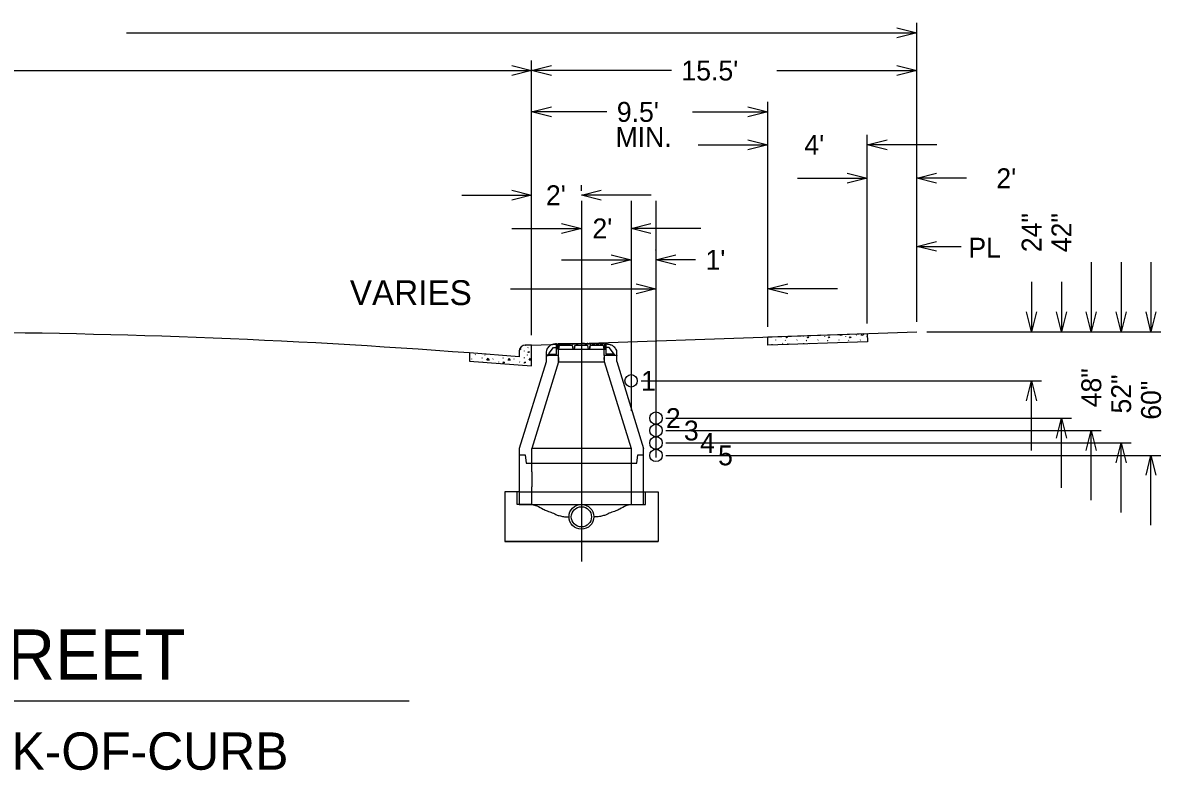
# Model space of a CAD drawing. Extents: x 524397 to 525117, y 3701341 to 3701821.
# Drawn here: x 524541.9 to 524633.5, y 3701606.9 to 3701667.1 of the extents above; entities that cross this region are included whole.
import ezdxf

# ---------------------------------------------------------------- set-up
doc = ezdxf.new("R2010")
doc.units = 0
doc.layers.add('Level 1', color=7, linetype='Continuous')
doc.layers.add('Level 11', color=7, linetype='Continuous')

msp = doc.modelspace()

# ---------------------------------------------------------------- linework, layer by layer
at = {"layer": 'Level 1'}
msp.add_line((524483.617, 3701612.509), (524573.018, 3701612.509), dxfattribs=at)
at = {"layer": 'Level 11'}
for p, q in [((524550.265, 3701666.282), (524613.852, 3701666.282)), ((524612.251, 3701666.682), (524613.852, 3701666.282)), ((524613.852, 3701666.282), (524612.251, 3701665.882)), ((524613.852, 3701643.021), (524613.852, 3701667.083)), ((524581.27, 3701663.64), (524582.871, 3701663.24)), ((524582.871, 3701641.938), (524582.871, 3701664.041)), ((524582.871, 3701663.24), (524584.472, 3701663.64)), ((524612.251, 3701663.64), (524613.852, 3701663.24)), ((524613.852, 3701643.021), (524613.852, 3701664.041)), ((524536.524, 3701663.24), (524582.871, 3701663.24)), ((524582.871, 3701663.24), (524581.27, 3701662.84)), ((524594.12, 3701663.24), (524582.871, 3701663.24)), ((524584.472, 3701662.84), (524582.871, 3701663.24)), ((524602.603, 3701663.24), (524613.852, 3701663.24)), ((524613.852, 3701663.24), (524612.251, 3701662.84)), ((524582.871, 3701641.937), (524582.871, 3701660.711)), ((524601.871, 3701642.602), (524601.871, 3701660.711)), ((524582.871, 3701659.911), (524584.472, 3701660.311)), ((524588.923, 3701659.911), (524582.871, 3701659.911)), ((524584.472, 3701659.511), (524582.871, 3701659.911)), ((524595.819, 3701659.911), (524601.871, 3701659.911)), ((524600.27, 3701660.311), (524601.871, 3701659.911)), ((524601.871, 3701659.911), (524600.27, 3701659.511)), ((524601.871, 3701652.457), (524601.871, 3701658.057)), ((524609.866, 3701642.881), (524609.866, 3701658.057)), ((524596.267, 3701657.256), (524601.871, 3701657.256)), ((524600.27, 3701657.656), (524601.871, 3701657.256)), ((524601.871, 3701657.256), (524600.27, 3701656.856)), ((524609.866, 3701657.256), (524611.467, 3701657.656)), ((524615.47, 3701657.256), (524609.866, 3701657.256)), ((524611.467, 3701656.856), (524609.866, 3701657.256)), ((524609.866, 3701651.269), (524609.866, 3701655.37)), ((524613.853, 3701643.021), (524613.853, 3701655.37)), ((524604.263, 3701654.569), (524609.866, 3701654.569)), ((524608.265, 3701654.97), (524609.866, 3701654.569)), ((524609.866, 3701654.569), (524608.265, 3701654.169)), ((524613.853, 3701654.569), (524615.454, 3701654.97)), ((524617.855, 3701654.569), (524613.853, 3701654.569)), ((524615.454, 3701654.169), (524613.853, 3701654.569)), ((524581.27, 3701653.603), (524582.871, 3701653.202)), ((524582.871, 3701641.937), (524582.871, 3701654.003)), ((524586.871, 3701653.553), (524586.871, 3701654.003)), ((524586.871, 3701653.202), (524588.472, 3701653.603)), ((524577.267, 3701653.202), (524582.871, 3701653.202)), ((524582.871, 3701653.202), (524581.27, 3701652.802)), ((524592.475, 3701653.202), (524586.871, 3701653.202)), ((524588.472, 3701652.802), (524586.871, 3701653.202)), ((524586.871, 3701652.752), (524586.871, 3701623.725)), ((524590.871, 3701652.752), (524590.871, 3701635.855)), ((524592.871, 3701652.752), (524592.871, 3701632.088)), ((524585.27, 3701650.933), (524586.871, 3701650.533)), ((524590.871, 3701650.533), (524592.472, 3701650.933)), ((524581.267, 3701650.533), (524586.871, 3701650.533)), ((524586.871, 3701650.533), (524585.27, 3701650.133)), ((524586.871, 3701649.77), (524586.871, 3701649.733)), ((524596.475, 3701650.533), (524590.871, 3701650.533)), ((524592.472, 3701650.133), (524590.871, 3701650.533)), ((524590.871, 3701649.812), (524590.871, 3701649.733)), ((524592.871, 3701648.778), (524592.871, 3701648.806)), ((524613.852, 3701649.092), (524615.453, 3701649.492)), ((524613.852, 3701649.092), (524617.42, 3701649.092)), ((524615.453, 3701648.692), (524613.852, 3701649.092)), ((524585.267, 3701648.005), (524590.871, 3701648.005)), ((524589.27, 3701648.406), (524590.871, 3701648.005)), ((524590.871, 3701648.005), (524589.27, 3701647.605)), ((524592.871, 3701648.005), (524594.472, 3701648.406)), ((524596.056, 3701648.005), (524592.871, 3701648.005)), ((524594.472, 3701647.605), (524592.871, 3701648.005)), ((524590.871, 3701647.261), (524590.871, 3701647.205)), ((524627.895, 3701647.824), (524627.895, 3701642.22)), ((524630.297, 3701647.824), (524630.297, 3701642.22)), ((524632.698, 3701647.824), (524632.698, 3701642.22)), ((524591.27, 3701646.08), (524592.871, 3701645.68)), ((524601.871, 3701643.402), (524601.871, 3701646.48)), ((524601.871, 3701645.68), (524603.472, 3701646.08)), ((524623.093, 3701646.223), (524623.093, 3701642.22)), ((524625.494, 3701646.223), (524625.494, 3701642.22)), ((524581.162, 3701645.68), (524592.871, 3701645.68)), ((524592.871, 3701645.68), (524591.27, 3701645.28)), ((524607.475, 3701645.68), (524601.871, 3701645.68)), ((524603.472, 3701645.28), (524601.871, 3701645.68)), ((524592.871, 3701644.92), (524592.871, 3701644.88)), ((524623.093, 3701642.22), (524622.692, 3701643.821)), ((524623.493, 3701643.821), (524623.093, 3701642.22)), ((524625.494, 3701642.22), (524625.094, 3701643.821)), ((524625.894, 3701643.821), (524625.494, 3701642.22)), ((524627.895, 3701642.22), (524627.495, 3701643.821)), ((524628.296, 3701643.821), (524627.895, 3701642.22)), ((524630.297, 3701642.22), (524629.897, 3701643.821)), ((524630.697, 3701643.821), (524630.297, 3701642.22)), ((524632.698, 3701642.22), (524632.298, 3701643.821)), ((524633.098, 3701643.821), (524632.698, 3701642.22)), ((524582.871, 3701641.137), (524613.852, 3701642.221)), ((524601.871, 3701641.802), (524609.866, 3701642.081)), ((524601.871, 3701641.141), (524601.871, 3701641.802)), ((524602.504, 3701641.536), (524602.518, 3701641.568)), ((524603.027, 3701641.842), (524603.028, 3701641.826)), ((524603.267, 3701641.536), (524603.281, 3701641.514)), ((524603.281, 3701641.528), (524603.296, 3701641.506)), ((524604.205, 3701641.536), (524604.219, 3701641.568)), ((524604.726, 3701641.858), (524604.73, 3701641.826)), ((524604.969, 3701641.536), (524604.983, 3701641.514)), ((524604.983, 3701641.528), (524604.997, 3701641.506)), ((524605.907, 3701641.536), (524605.921, 3701641.568)), ((524606.428, 3701641.858), (524606.431, 3701641.826)), ((524606.67, 3701641.536), (524606.684, 3701641.514)), ((524606.684, 3701641.528), (524606.699, 3701641.506)), ((524607.285, 3701641.948), (524607.299, 3701641.98)), ((524607.608, 3701641.536), (524607.622, 3701641.568)), ((524608.129, 3701641.858), (524608.133, 3701641.826)), ((524608.372, 3701641.536), (524608.386, 3701641.514)), ((524608.386, 3701641.528), (524608.4, 3701641.506)), ((524608.986, 3701641.948), (524609.001, 3701641.98)), ((524609.31, 3701641.536), (524609.324, 3701641.568)), ((524609.831, 3701641.858), (524609.834, 3701641.826)), ((524609.866, 3701642.081), (524609.889, 3701641.421)), ((524614.653, 3701642.22), (524623.893, 3701642.22)), ((524614.653, 3701642.22), (524626.294, 3701642.22)), ((524614.653, 3701642.22), (524628.696, 3701642.22)), ((524614.653, 3701642.22), (524631.097, 3701642.22)), ((524614.653, 3701642.22), (524633.499, 3701642.22)), ((524581.871, 3701640.675), (524581.871, 3701640.213)), ((524582.26, 3701640.689), (524582.263, 3701640.657)), ((524582.871, 3701641.138), (524582.358, 3701641.138)), ((524582.358, 3701641.138), (524582.371, 3701641.138)), ((524582.577, 3701640.924), (524582.591, 3701640.956)), ((524582.871, 3701639.476), (524582.871, 3701641.138)), ((524584.289, 3701640.507), (524584.639, 3701640.945)), ((524584.639, 3701640.945), (524584.872, 3701640.944)), ((524584.872, 3701641.235), (524584.872, 3701641.235)), ((524584.872, 3701641.235), (524584.955, 3701641.235)), ((524584.872, 3701640.944), (524584.872, 3701641.235)), ((524584.872, 3701640.403), (524584.872, 3701640.944)), ((524584.955, 3701640.819), (524584.955, 3701641.235)), ((524585.038, 3701640.819), (524584.955, 3701640.819)), ((524584.997, 3701641.235), (524584.997, 3701640.819)), ((524585.039, 3701641.235), (524584.997, 3701641.235)), ((524584.997, 3701641.235), (524585.039, 3701641.235)), ((524584.997, 3701640.819), (524584.997, 3701641.235)), ((524584.997, 3701640.819), (524588.744, 3701640.819)), ((524585.038, 3701640.819), (524584.997, 3701640.819)), ((524585.038, 3701640.819), (524585.09, 3701641.111)), ((524585.09, 3701641.111), (524585.038, 3701640.819)), ((524585.038, 3701640.319), (524585.038, 3701640.819)), ((524585.039, 3701641.235), (524585.054, 3701641.277)), ((524585.039, 3701641.235), (524585.054, 3701641.277)), ((524585.054, 3701641.277), (524585.117, 3701641.277)), ((524585.054, 3701641.277), (524585.117, 3701641.277)), ((524586.153, 3701641.111), (524585.09, 3701641.111)), ((524586.153, 3701641.111), (524585.09, 3701641.111)), ((524585.132, 3701641.235), (524585.117, 3701641.277)), ((524585.117, 3701641.277), (524585.132, 3701641.235)), ((524585.363, 3701641.235), (524585.132, 3701641.235)), ((524585.132, 3701641.235), (524585.363, 3701641.235)), ((524585.363, 3701641.235), (524585.378, 3701641.277)), ((524585.363, 3701641.235), (524585.378, 3701641.277)), ((524585.378, 3701641.277), (524585.438, 3701641.277)), ((524585.378, 3701641.277), (524585.438, 3701641.277)), ((524585.453, 3701641.235), (524585.438, 3701641.277)), ((524585.438, 3701641.277), (524585.453, 3701641.235)), ((524585.679, 3701641.235), (524585.453, 3701641.235)), ((524585.453, 3701641.235), (524585.679, 3701641.235)), ((524585.679, 3701641.235), (524585.694, 3701641.277)), ((524585.679, 3701641.235), (524585.694, 3701641.277)), ((524585.694, 3701641.277), (524585.762, 3701641.277)), ((524585.694, 3701641.277), (524585.762, 3701641.277)), ((524585.777, 3701641.235), (524585.762, 3701641.277)), ((524585.762, 3701641.277), (524585.777, 3701641.235)), ((524586.006, 3701641.235), (524585.777, 3701641.235)), ((524585.777, 3701641.235), (524586.006, 3701641.235)), ((524586.006, 3701641.235), (524586.022, 3701641.277)), ((524586.006, 3701641.235), (524586.022, 3701641.277)), ((524586.022, 3701641.277), (524586.087, 3701641.277)), ((524586.022, 3701641.277), (524586.087, 3701641.277)), ((524586.102, 3701641.235), (524586.087, 3701641.277)), ((524586.087, 3701641.277), (524586.102, 3701641.235)), ((524586.329, 3701641.235), (524586.102, 3701641.235)), ((524586.102, 3701641.235), (524586.329, 3701641.235)), ((524586.204, 3701640.819), (524586.153, 3701641.111)), ((524586.204, 3701640.819), (524586.153, 3701641.111)), ((524586.288, 3701640.819), (524586.204, 3701640.819)), ((524586.288, 3701640.819), (524586.339, 3701641.111)), ((524586.339, 3701641.111), (524586.288, 3701640.819)), ((524586.329, 3701641.235), (524586.344, 3701641.277)), ((524586.329, 3701641.235), (524586.344, 3701641.277)), ((524587.402, 3701641.111), (524586.339, 3701641.111)), ((524587.402, 3701641.111), (524586.339, 3701641.111)), ((524586.344, 3701641.277), (524586.402, 3701641.277)), ((524586.344, 3701641.277), (524586.402, 3701641.277)), ((524586.418, 3701641.235), (524586.402, 3701641.277)), ((524586.402, 3701641.277), (524586.418, 3701641.235)), ((524586.604, 3701641.235), (524586.418, 3701641.235)), ((524586.418, 3701641.235), (524586.604, 3701641.235)), ((524586.604, 3701641.235), (524586.62, 3701641.277)), ((524586.604, 3701641.235), (524586.62, 3701641.277)), ((524586.62, 3701641.277), (524586.87, 3701641.277)), ((524586.62, 3701641.277), (524587.122, 3701641.277)), ((524587.122, 3701641.277), (524586.87, 3701641.277)), ((524587.137, 3701641.235), (524587.122, 3701641.277)), ((524587.122, 3701641.277), (524587.137, 3701641.235)), ((524587.324, 3701641.235), (524587.137, 3701641.235)), ((524587.137, 3701641.235), (524587.324, 3701641.235)), ((524587.324, 3701641.235), (524587.339, 3701641.277)), ((524587.324, 3701641.235), (524587.339, 3701641.277)), ((524587.397, 3701641.277), (524587.339, 3701641.277)), ((524587.339, 3701641.277), (524587.397, 3701641.277)), ((524587.412, 3701641.235), (524587.397, 3701641.277)), ((524587.397, 3701641.277), (524587.412, 3701641.235)), ((524587.454, 3701640.819), (524587.402, 3701641.111)), ((524587.454, 3701640.819), (524587.402, 3701641.111)), ((524587.639, 3701641.235), (524587.412, 3701641.235)), ((524587.412, 3701641.235), (524587.639, 3701641.235)), ((524587.537, 3701640.819), (524587.454, 3701640.819)), ((524587.537, 3701640.819), (524587.588, 3701641.111)), ((524587.588, 3701641.111), (524587.537, 3701640.819)), ((524588.651, 3701641.111), (524587.588, 3701641.111)), ((524588.432, 3701641.111), (524587.588, 3701641.111)), ((524587.639, 3701641.235), (524587.655, 3701641.277)), ((524587.639, 3701641.235), (524587.655, 3701641.277)), ((524587.72, 3701641.277), (524587.655, 3701641.277)), ((524587.655, 3701641.277), (524587.72, 3701641.277)), ((524587.735, 3701641.235), (524587.72, 3701641.277)), ((524587.72, 3701641.277), (524587.735, 3701641.235)), ((524587.964, 3701641.235), (524587.735, 3701641.235)), ((524587.735, 3701641.235), (524587.964, 3701641.235)), ((524587.964, 3701641.235), (524587.979, 3701641.277)), ((524587.964, 3701641.235), (524587.979, 3701641.277)), ((524588.047, 3701641.277), (524587.979, 3701641.277)), ((524587.979, 3701641.277), (524588.047, 3701641.277)), ((524588.062, 3701641.235), (524588.047, 3701641.277)), ((524588.047, 3701641.277), (524588.062, 3701641.235)), ((524588.289, 3701641.235), (524588.062, 3701641.235)), ((524588.062, 3701641.235), (524588.289, 3701641.235)), ((524588.289, 3701641.235), (524588.303, 3701641.277)), ((524588.289, 3701641.235), (524588.303, 3701641.277)), ((524588.363, 3701641.277), (524588.303, 3701641.277)), ((524588.303, 3701641.277), (524588.363, 3701641.277)), ((524588.378, 3701641.235), (524588.363, 3701641.277)), ((524588.363, 3701641.277), (524588.378, 3701641.235)), ((524588.609, 3701641.235), (524588.378, 3701641.235)), ((524588.378, 3701641.235), (524588.432, 3701641.235)), ((524588.432, 3701641.235), (524588.432, 3701641.111)), ((524588.432, 3701641.235), (524588.432, 3701641.111)), ((524588.557, 3701641.235), (524588.557, 3701641.111)), ((524588.557, 3701641.235), (524588.609, 3701641.235)), ((524588.557, 3701641.111), (524588.557, 3701641.235)), ((524588.651, 3701641.111), (524588.557, 3701641.111)), ((524588.609, 3701641.235), (524588.625, 3701641.277)), ((524588.609, 3701641.235), (524588.625, 3701641.277)), ((524588.687, 3701641.277), (524588.625, 3701641.277)), ((524588.625, 3701641.277), (524588.687, 3701641.277)), ((524588.703, 3701640.819), (524588.651, 3701641.111)), ((524588.703, 3701640.819), (524588.651, 3701641.111)), ((524588.702, 3701641.235), (524588.687, 3701641.277)), ((524588.687, 3701641.277), (524588.702, 3701641.235)), ((524588.744, 3701641.235), (524588.702, 3701641.235)), ((524588.702, 3701641.235), (524588.744, 3701641.235)), ((524588.703, 3701640.319), (524588.703, 3701640.819)), ((524588.703, 3701640.819), (524588.786, 3701640.819)), ((524588.744, 3701640.819), (524588.703, 3701640.819)), ((524588.744, 3701641.235), (524588.744, 3701640.819)), ((524588.744, 3701641.235), (524588.744, 3701640.819)), ((524588.786, 3701640.819), (524588.786, 3701641.235)), ((524588.869, 3701641.235), (524588.786, 3701641.235)), ((524588.869, 3701640.944), (524588.869, 3701641.235)), ((524589.102, 3701640.945), (524588.869, 3701640.944)), ((524588.869, 3701640.403), (524588.869, 3701640.944)), ((524589.452, 3701640.507), (524589.102, 3701640.945)), ((524609.889, 3701641.421), (524601.871, 3701641.141)), ((524602.216, 3701641.191), (524602.23, 3701641.223)), ((524603.058, 3701641.272), (524603.072, 3701641.304)), ((524603.927, 3701641.213), (524603.932, 3701641.223)), ((524604.759, 3701641.272), (524604.773, 3701641.304)), ((524606.474, 3701641.302), (524606.475, 3701641.304)), ((524581.871, 3701640.213), (524577.871, 3701640.515)), ((524577.871, 3701640.515), (524577.871, 3701639.853)), ((524577.871, 3701639.853), (524582.871, 3701639.476)), ((524578.048, 3701640.021), (524578.062, 3701640.053)), ((524578.336, 3701640.366), (524578.35, 3701640.398)), ((524578.89, 3701640.103), (524578.904, 3701640.135)), ((524579.099, 3701640.366), (524579.113, 3701640.345)), ((524579.113, 3701640.358), (524579.128, 3701640.337)), ((524579.749, 3701640.021), (524579.764, 3701640.053)), ((524580.193, 3701639.794), (524580.208, 3701639.773)), ((524580.591, 3701640.103), (524580.605, 3701640.135)), ((524581.451, 3701640.021), (524581.465, 3701640.053)), ((524584.028, 3701639.786), (524581.878, 3701632.819)), ((524581.895, 3701639.794), (524581.909, 3701639.773)), ((524582.293, 3701640.103), (524582.307, 3701640.135)), ((524582.502, 3701640.366), (524582.516, 3701640.345)), ((524582.516, 3701640.358), (524582.531, 3701640.337)), ((524585.028, 3701639.787), (524582.877, 3701632.819)), ((524584.028, 3701640.319), (524584.028, 3701639.786)), ((524585.038, 3701640.319), (524584.028, 3701640.319)), ((524584.028, 3701640.319), (524584.205, 3701640.319)), ((524584.205, 3701640.319), (524584.205, 3701640.403)), ((524584.205, 3701640.403), (524584.289, 3701640.403)), ((524584.289, 3701640.403), (524584.289, 3701640.507)), ((524584.289, 3701640.403), (524584.872, 3701640.403)), ((524585.028, 3701639.787), (524585.028, 3701640.319)), ((524585.028, 3701640.153), (524585.028, 3701639.827)), ((524585.028, 3701639.787), (524588.713, 3701639.787)), ((524589.713, 3701640.319), (524588.703, 3701640.319)), ((524588.713, 3701640.319), (524588.713, 3701639.82)), ((524588.713, 3701639.986), (524588.713, 3701640.16)), ((524588.713, 3701639.82), (524590.873, 3701632.824)), ((524589.713, 3701640.319), (524588.714, 3701640.319)), ((524589.452, 3701640.403), (524588.869, 3701640.403)), ((524589.452, 3701640.403), (524589.452, 3701640.507)), ((524589.535, 3701640.403), (524589.452, 3701640.403)), ((524589.535, 3701640.319), (524589.535, 3701640.403)), ((524589.713, 3701640.319), (524589.535, 3701640.319)), ((524589.713, 3701639.82), (524589.713, 3701640.319)), ((524589.713, 3701639.82), (524591.872, 3701632.824)), ((524591.671, 3701638.27), (524623.893, 3701638.27)), ((524622.692, 3701636.669), (524623.093, 3701638.27)), ((524623.093, 3701632.667), (524623.093, 3701638.27)), ((524623.093, 3701638.27), (524623.493, 3701636.669)), ((524593.671, 3701635.27), (524626.294, 3701635.27)), ((524625.094, 3701633.669), (524625.494, 3701635.27)), ((524625.494, 3701629.667), (524625.494, 3701635.27)), ((524625.494, 3701635.27), (524625.894, 3701633.669)), ((524593.671, 3701634.27), (524628.696, 3701634.27)), ((524627.495, 3701632.669), (524627.895, 3701634.27)), ((524627.895, 3701628.667), (524627.895, 3701634.27)), ((524627.895, 3701634.27), (524628.296, 3701632.669)), ((524593.671, 3701633.27), (524631.097, 3701633.27)), ((524629.897, 3701631.669), (524630.297, 3701633.27)), ((524630.297, 3701627.667), (524630.297, 3701633.27)), ((524630.297, 3701633.27), (524630.697, 3701631.669)), ((524581.878, 3701632.819), (524581.878, 3701631.658)), ((524581.878, 3701632.526), (524581.878, 3701632.324)), ((524581.878, 3701632.324), (524582.336, 3701632.324)), ((524581.878, 3701632.324), (524582.336, 3701632.324)), ((524581.878, 3701632.324), (524581.878, 3701630.937)), ((524582.336, 3701632.324), (524582.419, 3701631.658)), ((524582.336, 3701632.324), (524582.419, 3701631.658)), ((524590.873, 3701632.823), (524582.877, 3701632.819)), ((524582.877, 3701631.658), (524582.877, 3701632.819)), ((524582.877, 3701632.324), (524582.877, 3701632.526)), ((524582.877, 3701630.937), (524582.877, 3701632.324)), ((524590.873, 3701632.824), (524590.873, 3701631.658)), ((524590.873, 3701632.824), (524590.873, 3701632.324)), ((524590.873, 3701632.526), (524590.873, 3701632.324)), ((524590.873, 3701632.526), (524590.873, 3701632.324)), ((524590.873, 3701632.324), (524590.873, 3701628.327)), ((524590.873, 3701632.324), (524590.873, 3701628.327)), ((524591.331, 3701631.658), (524591.414, 3701632.324)), ((524591.331, 3701631.658), (524591.414, 3701632.324)), ((524591.414, 3701632.324), (524591.872, 3701632.324)), ((524591.414, 3701632.324), (524591.872, 3701632.324)), ((524591.414, 3701632.324), (524591.872, 3701632.324)), ((524591.872, 3701632.324), (524591.872, 3701632.824)), ((524591.872, 3701632.324), (524591.872, 3701632.824)), ((524591.872, 3701628.327), (524591.872, 3701632.526)), ((524591.872, 3701631.658), (524591.872, 3701632.324)), ((524581.878, 3701631.936), (524581.878, 3701628.327)), ((524582.419, 3701631.658), (524582.877, 3701631.658)), ((524582.419, 3701631.658), (524582.877, 3701631.658)), ((524582.877, 3701631.658), (524590.873, 3701631.658)), ((524582.877, 3701631.658), (524590.873, 3701631.658)), ((524590.873, 3701631.658), (524591.331, 3701631.658)), ((524590.873, 3701631.658), (524591.331, 3701631.658)), ((524593.671, 3701632.27), (524633.499, 3701632.27)), ((524632.298, 3701630.669), (524632.698, 3701632.27)), ((524632.698, 3701626.667), (524632.698, 3701632.27)), ((524632.698, 3701632.27), (524633.098, 3701630.669)), ((524582.877, 3701630.937), (524582.877, 3701629.753)), ((524582.877, 3701628.327), (524582.877, 3701629.753)), ((524581.878, 3701629.326), (524580.712, 3701629.326)), ((524580.712, 3701629.326), (524580.712, 3701625.329)), ((524581.712, 3701628.327), (524581.712, 3701629.326)), ((524581.878, 3701629.326), (524591.872, 3701629.326)), ((524591.872, 3701629.326), (524593.038, 3701629.326)), ((524592.039, 3701628.327), (524592.039, 3701629.326)), ((524593.038, 3701629.326), (524593.038, 3701625.329)), ((524581.878, 3701628.327), (524581.712, 3701628.327)), ((524581.878, 3701628.327), (524581.712, 3701628.327)), ((524581.878, 3701628.327), (524582.877, 3701628.327)), ((524582.877, 3701628.327), (524581.878, 3701628.327)), ((524582.877, 3701628.327), (524581.878, 3701628.327)), ((524582.877, 3701628.327), (524590.873, 3701628.327)), ((524590.873, 3701628.327), (524591.872, 3701628.327)), ((524590.873, 3701628.327), (524591.872, 3701628.327)), ((524591.872, 3701628.327), (524592.039, 3701628.327)), ((524593.038, 3701625.329), (524580.712, 3701625.329)), ((524580.712, 3701625.329), (524593.038, 3701625.329))]:
    msp.add_line(p, q, dxfattribs=at)
for points in [[(524603.349, 3701641.72), (524603.392, 3701641.809), (524603.463, 3701641.756), (524603.349, 3701641.72)], [(524605.051, 3701641.72), (524605.093, 3701641.809), (524605.164, 3701641.756), (524605.051, 3701641.72)], [(524606.015, 3701641.911), (524606.02, 3701641.947)], [(524606.099, 3701641.949), (524606.019, 3701641.912)], [(524606.752, 3701641.72), (524606.795, 3701641.809), (524606.866, 3701641.756), (524606.752, 3701641.72)], [(524607.717, 3701641.911), (524607.73, 3701642.006)], [(524607.845, 3701642.01), (524607.872, 3701641.983), (524607.72, 3701641.912)], [(524608.454, 3701641.72), (524608.496, 3701641.809), (524608.567, 3701641.756), (524608.454, 3701641.72)], [(524609.418, 3701641.911), (524609.44, 3701642.066)], [(524609.491, 3701642.068), (524609.574, 3701641.983), (524609.422, 3701641.912)], [(524581.935, 3701640.884), (524582.003, 3701640.813), (524581.898, 3701640.765)], [(524582.584, 3701640.551), (524582.627, 3701640.64), (524582.698, 3701640.587), (524582.584, 3701640.551)], [(524601.871, 3701641.189), (524601.892, 3701641.142)], [(524603.492, 3701641.198), (524603.534, 3701641.276), (524603.567, 3701641.201)], [(524605.226, 3701641.258), (524605.235, 3701641.276), (524605.243, 3701641.259)], [(524578.9, 3701639.776), (524578.907, 3701639.791), (524578.93, 3701639.773)], [(524579.27, 3701639.926), (524579.366, 3701640.107), (524579.44, 3701639.94), (524579.273, 3701639.926)], [(524580.566, 3701639.702), (524580.609, 3701639.791), (524580.68, 3701639.737), (524580.566, 3701639.702)], [(524580.971, 3701639.926), (524581.067, 3701640.107), (524581.142, 3701639.94), (524580.975, 3701639.926)], [(524582.268, 3701639.702), (524582.31, 3701639.791), (524582.381, 3701639.737), (524582.268, 3701639.702)], [(524582.673, 3701639.926), (524582.769, 3701640.107), (524582.843, 3701639.94), (524582.676, 3701639.926)]]:
    msp.add_lwpolyline(points, dxfattribs=at)
for centre, radius in [((524590.871, 3701638.27), 0.5), ((524592.871, 3701635.27), 0.5), ((524592.871, 3701634.27), 0.5), ((524592.871, 3701633.27), 0.5), ((524592.871, 3701632.27), 0.5), ((524586.875, 3701627.327), 0.999), ((524586.875, 3701627.327), 0.814)]:
    msp.add_circle(centre, radius, dxfattribs=at)
for centre, radius, start, end in [((524533.871, 3701057.733), 584.44, 85.68236, 94.31764), ((524582.364, 3701640.643), 0.494, 89.23325, 176.29205)]:
    msp.add_arc(centre, radius, start, end, dxfattribs=at)
for points in [[(524584.872, 3701641.235), (524584.799, 3701641.235), (524584.72, 3701641.224), (524584.651, 3701641.212), (524584.592, 3701641.2), (524584.528, 3701641.172), (524584.47, 3701641.159), (524584.327, 3701641.079), (524584.223, 3701640.994), (524584.132, 3701640.875), (524584.056, 3701640.711), (524584.035, 3701640.479), (524584.028, 3701640.319)], [(524588.869, 3701641.235), (524588.942, 3701641.235), (524589.021, 3701641.224), (524589.09, 3701641.212), (524589.149, 3701641.2), (524589.213, 3701641.172), (524589.272, 3701641.159), (524589.415, 3701641.079), (524589.518, 3701640.994), (524589.609, 3701640.875), (524589.685, 3701640.711), (524589.706, 3701640.479), (524589.713, 3701640.319)], [(524582.877, 3701628.327), (524583.292, 3701628.202), (524583.795, 3701627.951), (524584.11, 3701627.804), (524584.53, 3701627.657), (524584.929, 3701627.469), (524585.265, 3701627.385), (524585.601, 3701627.322), (524585.876, 3701627.327)], [(524590.873, 3701628.327), (524590.459, 3701628.202), (524589.955, 3701627.951), (524589.64, 3701627.804), (524589.22, 3701627.657), (524588.821, 3701627.469), (524588.485, 3701627.385), (524588.149, 3701627.322), (524587.874, 3701627.327)]]:
    msp.add_spline(points, degree=3, dxfattribs=at)

# ---------------------------------------------------------------- texts
at = {"layer": 'Level 1'}
msp.add_text('UTILITY LOCATIONS - STREET', height=4.03623, dxfattribs=at).set_placement((524476.158, 3701614.226))
at = {"layer": 'Level 11'}
for s, height, p in [("15.5'", 1.601, (524594.92, 3701662.44)), ("9.5'", 1.601, (524589.724, 3701659.11)), ('MIN.', 1.601, (524589.618, 3701657.092)), ("4'", 1.601, (524604.81, 3701656.456)), ("2'", 1.601, (524620.257, 3701653.769)), ("2'", 1.601, (524584.021, 3701652.402)), ("2'", 1.601, (524587.76, 3701649.733)), ('PL', 1.601, (524618.009, 3701648.18)), ("1'", 1.601, (524596.856, 3701647.205)), ('VARIES', 2, (524568.246, 3701644.366)), ('1', 1.601, (524591.671, 3701637.47)), ('2', 1.601, (524593.671, 3701634.47)), ('3', 1.601, (524595.121, 3701633.47)), ('4', 1.601, (524596.42, 3701632.47)), ('5', 1.601, (524597.87, 3701631.47)), ('SIDEWALKS SET BACK FROM BACK-OF-CURB', 3, (524474.372, 3701606.978))]:
    msp.add_text(s, height=height, dxfattribs=at).set_placement(p)
for s, p in [('24"', (524623.893, 3701648.624)), ('42"', (524626.294, 3701648.624)), ('48"', (524628.696, 3701636.14)), ('52"', (524631.097, 3701635.64)), ('60"', (524633.499, 3701635.14))]:
    msp.add_text(s, height=1.601, rotation=90, dxfattribs=at).set_placement(p)

doc.saveas('drawing.dxf')
